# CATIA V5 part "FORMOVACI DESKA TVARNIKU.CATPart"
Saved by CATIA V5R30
Part number: FORMOVACI DESKA TVARNIKU
Bounding box of the stored display mesh (mm): x 0 to 56, y -248 to 248, z -173 to 173
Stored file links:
  C:\Users\ondra\Desktop\PŘÍLOHA P III\CATIA\FORMOVACI DESKA TVARNIKU.CATPart
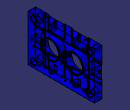
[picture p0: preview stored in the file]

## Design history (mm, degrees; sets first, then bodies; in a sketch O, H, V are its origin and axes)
Set1
  DatumSurface1 to DatumSurface42 "K20/346x"
  Plane1: type Tangent, Support DatumSurface41, RefPoint vertex [face of DatumSurface42]
  Plane2: type Tangent, Support DatumSurface39, RefPoint vertex [face of DatumSurface38]
  Plane3: type Offset, RefPlane yz-plane, Offset 56
  Join1: Elements (DatumSurface1; DatumSurface2; DatumSurface3; DatumSurface4; DatumSurface5; DatumSurface6; DatumSurface7; DatumSurface8; DatumSurface9; DatumSurface10; DatumSurface11; DatumSurface12; DatumSurface13; DatumSurface14; DatumSurface15; DatumSurface16; DatumSurface17; DatumSurface18; DatumSurface19; DatumSurface20; DatumSurface21; DatumSurface22; DatumSurface23; DatumSurface24; DatumSurface25; DatumSurface26; DatumSurface27; DatumSurface28; DatumSurface29; DatumSurface30; DatumSurface31; DatumSurface32; DatumSurface33; DatumSurface34; DatumSurface35; DatumSurface36; DatumSurface37; DatumSurface38; DatumSurface39; DatumSurface40; DatumSurface41; DatumSurface42)
Body1 (main body)
  DatumPoint1
  CloseSurface1: CloseElement Join1
  Sketch1 on {plane type Tangent, Support face of CloseSurface1, RefPoint vertex of DatumPoint1}, origin (0, -88.524, 0), H (0, 1, 0), V (0, 0, -1)
    point P1 (0, 0)
    reference projected point E1 (0, 0) from vertex of DatumPoint1
    coincidence: E1 P1
  Hole1: placed by Sketch1, at (56, -88.524, 0) direction (-1, 0, 0), diameter 130, through (limit type 6), counterbore diameter 140, counterbore depth 10
  Sketch2, origin (0, 0, 0), H (0, 1, 0), V (0, 0, -1), geometry linked from another document
  UserPattern1: of Hole1, copies 2, at the points of Sketch2
  Fillet1: radius 1, on edge [face of Hole1 | face of Hole1] (x2); edge [face of UserPattern1 | face of UserPattern1]; face of UserPattern1
  Plane4: type Offset, RefPlane yz-plane, Offset 56
  Sketch3 on Plane4, origin (56, 0, 0), H (0, 1, 0), V (0, 0, 1)
    point P1 (0, 0)
    coincidence: P1 O
  Sketch4 on {plane type Tangent, Support face of CloseSurface1, RefPoint Sketch3.P1}, origin (56, 0, 0), H (0, 1, 0), V (0, 0, -1)
    point P1 (0, 0)
    reference projected point E1 (0, 0) from Sketch3.P1
    coincidence: E1 P1
  Hole2: placed by Sketch4, at (56, 0, 0) direction (-1, 0, 0), diameter 18, through (limit type 6), counterbore diameter 22, counterbore depth 6
  Sketch5 on Plane4, origin (56, 0, 0), H (0, 1, 0), V (0, 0, 1)
    reference projected circle E1 centre (0, 0) radius 11 from edge [face of Hole2 | face of CloseSurface1]
    line L1 (-2, 10.8167) -> (-2, 16.0167)
    point P1 (-2, 10.8167)
    line L2 (-2, 16.0167) -> (2, 16.0167)
    line L3 (2, 16.0167) -> (2, 10.8167)
    point P4 (2, 10.8167)
    line L4 (2, 10.8167) -> (-2, 10.8167)
    point P5 (2, 10.8167)
    length L2 = 4
    length L3 = 5.2
    coincidence: P1 E1, P4 E1, P5 L3, P5 E1, P4 P5
    vertical: L1 V, L3 V
    horizontal: L2 H
    symmetry: L1 L3 V
  Pocket1: profile Sketch5, direction (-1, 0, 0), length 6
  Sketch6, origin (-1.2715, 23.524, 0), H (0, 0, 1), V (1, 0, 0), geometry linked from another document
  Pocket2: profile Sketch6, direction (0, -1, 0), length 6.1, opposite side through (limit type 6)
  DatumSurface43
  Sketch7, origin (-1.2715, -23.524, 0), H (0, 0, -1), V (1, 0, 0), geometry linked from another document
  Pocket3: profile Sketch7, direction (0, 1, 0), length 6.1, opposite side through (limit type 6)
  DatumSurface44
  Sketch8 on face of DatumSurface43, origin (56.0003, 0, 0), H (0, 1, 0), V (0, 0, 1)
    reference projected circle E1 centre (88.524, 0) radius 70 from face of DatumSurface44
    line L1 (158.4794, -2.5) -> (165.4794, -2.5)
    point P1 (158.4794, -2.5)
    line L2 (165.4794, -2.5) -> (165.4794, 2.5)
    line L3 (165.4794, 2.5) -> (158.4794, 2.5)
    point P4 (158.4794, 2.5)
    line L4 (158.4794, 2.5) -> (158.4794, -2.5)
    length L2 = 5
    length L3 = 7
    coincidence: P1 E1, P4 E1
    horizontal: L1 H, L3 H
    vertical: L2 V, L4 V
    symmetry: L1 L3 H
  Pocket4: profile Sketch8, direction (-1, 0, 0), length 7
  DatumSurface45
  Mirror1: of Pocket4, about zx-plane
  DatumSurface46
  Sketch9 on face of DatumSurface45, origin (-66, 0, 0), H (0, 1, 0), V (0, 0, 1)
    reference projected circle E1 centre (88.524, 0) radius 70 from face of DatumSurface46
    line L1 (158.4794, -2.5) -> (165.4794, -2.5)
    point P1 (158.4794, -2.5)
    line L2 (165.4794, -2.5) -> (165.4794, 2.5)
    line L3 (165.4794, 2.5) -> (158.4794, 2.5)
    point P4 (158.4794, 2.5)
    line L4 (158.4794, 2.5) -> (158.4794, -2.5)
    point P5 (158.4794, -2.5)
    length L3 = 7
    length L2 = 5
    coincidence: P1 E1, P4 E1, P5 L1
    horizontal: L1 H, L3 H
    vertical: L2 V, L4 V
    symmetry: L3 L1 H
  Plane5: type Offset, RefPlane zx-plane, Offset 248, reversed
  DatumSurface47
  Sketch10 on Plane5, origin (0, -248, 0), H (-1, 0, 0), V (0, 0, 1)
  Pocket5: profile Sketch10, direction (0, 1, 0), length 71
  Plane6: type Offset, RefPlane xy-plane, Offset 173
  DatumSurface48
  DatumSurface49
  Sketch11 on Plane6, origin (0, 0, 173), H (1, 0, 0), V (0, 1, 0)
  Pocket6: profile Sketch11, direction (0, 0, -1), length 101.008
  Mirror2: of Pocket5, about zx-plane
  Mirror3: of Pocket6, about xy-plane
  DatumSurface50
  Sketch12 on face of Pocket6, origin (7.4573, 0, 0), H (0, -1, 0), V (0, 0, 1)
    point P1 (79.524, 153)
    line L1 (79.524, 153) -> (97.524, 153)
    line L2 (97.524, 153) -> (97.524, 118)
    line L3 (97.524, 118) -> (79.524, 118)
    line L4 (79.524, 118) -> (79.524, 153)
    point P2 (97.524, 153)
    point P3 (97.524, 118)
    point P4 (79.524, 118)
    reference projected line E1 (148.524, 173) -> (28.524, 173) from edge [face of CloseSurface1 | face of Pocket6]
    point P5 (97.524, -118)
    point P6 (97.524, -153)
    line L5 (97.524, -153) -> (97.524, -118)
    point P7 (79.524, -153)
    point P8 (79.524, -118)
    line L6 (79.524, -118) -> (79.524, -153)
    line L7 (79.524, -153) -> (97.524, -153)
    point P9 (79.524, -118)
    point P10 (97.524, -118)
    line L8 (97.524, -118) -> (79.524, -118)
    line L9 (233, -9) -> (198, -9)
    line L10 (198, -9) -> (198, 9)
    line L11 (198, 9) -> (233, 9)
    line L12 (233, 9) -> (233, -9)
    reference projected line E2 (248, -47.5) -> (248, 47.5) from edge [face of CloseSurface1 | face of Pocket5]
    reference projected circle E3 centre (88.524, 0) radius 70 from face of DatumSurface50
    construction line L13 (88.524, 0) -> (88.524, 20.512)
    point P15 (88.524, 0)
    length L4 = 35
    length L1 = 18
    distance L1 E1 = 20
    distance E2 L12 = 15
    length L11 = 35
    length L12 = 18
    horizontal: L1 H, L3 H, L9 H, L11 H
    vertical: L2 V, L4 V, L10 V, L12 V, L13 V
    symmetry: P3 P5 H, P2 P6 H, L2 L5 H, P1 P7 H, P4 P8 H, L4 L6 H, L1 L7 H, P4 P9 H, P3 P10 H, L3 L8 H, L9 L11 H, L4 L2 L13
    concentricity: P15 E3
    coincidence: P5 P10, P8 P9
  Pocket7: profile Sketch12, direction (1, 0, 0), length 43, opposite side through (limit type 6)
  Sketch13 on Plane6, origin (0, 0, 173), H (1, 0, 0), V (0, 1, 0)
    point P1 (13, 165)
    point P2 (13, -165)
    construction line L1 (13, -165) -> (13, 165)
    distance P2 P1 = 330
    vertical: L1 V
    symmetry: P2 P1 H
  Sketch14 on {plane type Tangent, Support face of CloseSurface1, RefPoint Sketch13.P2}, origin (28, -115, 173), H (1, 0, 0), V (0, -1, 0)
    point P1 (-15, 50)
    reference projected point E1 (-15, 50) from Sketch13.P2
    coincidence: E1 P1
  Hole3: placed by Sketch14, at (13, -165, 173) direction (0, 0, -1), diameter 8.376, through (limit type 6), counterbore diameter 16, counterbore depth 17, threaded "M10", thread diameter 10, thread depth 7, pitch 1.5
  Sketch15 on Plane5, origin (0, -248, 0), H (-1, 0, 0), V (0, 0, 1)
    point P1 (-13, -71)
    point P2 (-13, 71)
    construction line L1 (-13, -71) -> (-13, 71)
    reference projected line E1 (-56, -173) -> (-56, 173) from edge [face of CloseSurface1 | face of CloseSurface1]
    length L1 = 142
    distance P2 E1 = 43
    vertical: L1 V
    symmetry: P2 P1 H
  Sketch16 on {plane type Tangent, Support face of CloseSurface1, RefPoint Sketch15.P1}, origin (28, -248, -75), H (1, 0, 0), V (0, 0, -1)
    point P1 (-15, -4)
    reference projected point E1 (-15, -4) from Sketch15.P1
    coincidence: E1 P1
  Hole4: placed by Sketch16, at (13, -248, -71) direction (0, 1, 0), diameter 8.376, through (limit type 3), counterbore diameter 14, counterbore depth 3, threaded "M10", thread diameter 10, thread depth 9, pitch 1.5
  UserPattern2: of Hole4, copies 2, at the points of Sketch15
  Sketch17 on {plane type Tangent, Support face of CloseSurface1, RefPoint Sketch13.P1}, origin (12, 165, 173), H (1, 0, 0), V (0, -1, 0)
    point P1 (1, 0)
    reference projected point E1 (1, 0) from Sketch13.P1
    coincidence: E1 P1
  Hole5: placed by Sketch17, at (13, 165, 173) direction (0, 0, -1), diameter 8.376, through (limit type 3), counterbore diameter 14, counterbore depth 3, threaded "M10", thread diameter 10, thread depth 9, pitch 1.5
  Plane7: type Offset, RefPlane Plane5, Offset 496
  Plane8: type Offset, RefPlane Plane6, Offset 346, reversed
  Mirror4: of Pocket7, about zx-plane
  DatumSurface51 to DatumSurface58
  Sketch18 on face of Mirror2, origin (3.6725, 0, 0), H (0, -1, 0), V (0, 0, 1)
    reference projected circle E1 centre (-240, 41) radius 3.75 from face of DatumSurface51
    reference projected circle E3 centre (-185, 41) radius 3.75 from face of DatumSurface52
    reference projected circle E5 centre (-240, -41) radius 3.75 from face of DatumSurface53
    reference projected circle E7 centre (-185, -41) radius 3.75 from face of DatumSurface54
    reference projected circle E9 centre (185, 41) radius 3.75 from face of DatumSurface55
    reference projected circle E11 centre (240, 41) radius 3.75 from face of DatumSurface56
    reference projected circle E13 centre (185, -41) radius 3.75 from face of DatumSurface57
    reference projected circle E15 centre (240, -41) radius 3.75 from face of DatumSurface58
    point P1 (185, -41)
    point P2 (240, -41)
    point P3 (240, 41)
    point P4 (185, 41)
    point P5 (-240, -41)
    point P6 (-185, -41)
    point P7 (-185, 41)
    point P8 (-240, 41)
    concentricity: P1 E13, P2 E15, P3 E11, P4 E9, P5 E5, P6 E7, P7 E3, P8 E1
  Sketch19 on face of Mirror2, origin (3.6725, 240, -41), H (0, 1, 0), V (0, 0, -1)
    point P1 (0, 0)
    reference projected point E1 (0, 0) from Sketch18.P5
    coincidence: E1 P1
  Hole6: placed by Sketch19, at (3.6725, 240, -41) direction (1, 0, 0), diameter 4.134, depth 15, V-bottom angle 120, threaded "M5", thread diameter 5, thread depth 13, pitch 0.8
  UserPattern3: of Hole6, copies 8, at the points of Sketch18
  DatumSurface59 to DatumSurface74
  Sketch20 on face of Mirror3, origin (7.4573, 0, 0), H (0, -1, 0), V (0, 0, 1)
    reference projected circle E1 centre (-140.524, 163.9919) radius 4.4 from face of DatumSurface59
    reference projected circle E3 centre (-140.524, 79.9919) radius 4.4 from face of DatumSurface60
    reference projected circle E5 centre (-36.524, 79.9919) radius 4.4 from face of DatumSurface61
    reference projected circle E7 centre (-36.524, 163.9919) radius 4.4 from face of DatumSurface62
    reference projected circle E9 centre (36.524, 79.9919) radius 4.4 from face of DatumSurface63
    reference projected circle E11 centre (36.524, 163.9919) radius 4.4 from face of DatumSurface64
    reference projected circle E13 centre (140.524, 163.9919) radius 4.4 from face of DatumSurface65
    reference projected circle E15 centre (140.524, 79.9919) radius 4.4 from face of DatumSurface66
    reference projected circle E17 centre (36.524, -163.9919) radius 4.4 from face of DatumSurface67
    reference projected circle E19 centre (36.524, -79.9919) radius 4.4 from face of DatumSurface68
    reference projected circle E21 centre (140.524, -79.9919) radius 4.4 from face of DatumSurface69
    reference projected circle E23 centre (140.524, -163.9919) radius 4.4 from face of DatumSurface70
    reference projected circle E25 centre (-140.524, -163.9919) radius 4.4 from face of DatumSurface71
    reference projected circle E27 centre (-140.524, -79.9919) radius 4.4 from face of DatumSurface72
    reference projected circle E29 centre (-36.524, -79.9919) radius 4.4 from face of DatumSurface73
    reference projected circle E31 centre (-36.524, -163.9919) radius 4.4 from face of DatumSurface74
    point P1 (-140.524, -163.9919)
    point P2 (-140.524, -79.9919)
    point P3 (-36.524, -163.9919)
    point P4 (-36.524, -79.9919)
    point P5 (36.524, -79.9919)
    point P6 (36.524, -163.9919)
    point P7 (140.524, -163.9919)
    point P8 (140.524, -79.9919)
    point P9 (140.524, 79.9919)
    point P10 (140.524, 163.9919)
    point P11 (36.524, 163.9919)
    point P12 (36.524, 79.9919)
    point P13 (-140.524, 163.9919)
    point P14 (-36.524, 163.9919)
    point P15 (-36.524, 79.9919)
    point P16 (-140.524, 79.9919)
    concentricity: P1 E25, P2 E27, P3 E31, P4 E29, P5 E19, P6 E17, P7 E23, P8 E21, P9 E15, P10 E13, P11 E11, P12 E9, P13 E1, P14 E7, P15 E5, P16 E3
  Sketch21 on face of Mirror3, origin (7.4573, 140.524, -163.9919), H (0, 1, 0), V (0, 0, -1)
    point P1 (0, 0)
    reference projected point E1 (0, 0) from Sketch20.P1
    coincidence: E1 P1
  Hole7: placed by Sketch21, at (7.4573, 140.524, -163.9919) direction (1, 0, 0), diameter 4.917, depth 15, V-bottom angle 120, threaded "M6", thread diameter 6, thread depth 13, pitch 1
  UserPattern4: of Hole7, copies 16, at the points of Sketch20
  Plane9: type Offset, RefPlane yz-plane, Offset 4.328, reversed
  Plane10: type Offset, RefPlane yz-plane, Offset 2.543, reversed
  Plane11: type Offset, RefPlane zx-plane, Offset 88.254
  Plane12: type Offset, RefPlane zx-plane, Offset 88.254, reversed
  DatumCurve1
  DatumCurve2
  Sketch22 on face of Mirror2, origin (3.6725, 0, 0), H (0, -1, 0), V (0, 0, 1)
    reference projected line E1 (-243.5, 7) -> (-227.5, 7) from edge of DatumCurve1
    reference projected line E2 (-227.5, -7) -> (-243.5, -7) from edge of DatumCurve2
    reference projected line E3 (-248, -47.5) -> (-248, 47.5) from edge [face of Mirror2 | face of CloseSurface1]
    point P7 (-232.5199, -7)
    line L1 (-232.5199, -7) -> (-248, -7)
    line L2 (-248, -7) -> (-248, 7)
    line L3 (-248, 7) -> (-232.5199, 7)
    line L4 (-232.5199, 7) -> (-232.5199, -7)
    point P8 (-248, -7)
    point P9 (-248, 7)
    point P10 (-232.5199, 7)
    point P11 (248, -7)
    point P12 (232.5199, -7)
    line L5 (232.5199, -7) -> (248, -7)
    point P13 (248, 7)
    line L6 (248, -7) -> (248, 7)
    point P14 (232.5199, 7)
    line L7 (248, 7) -> (232.5199, 7)
    line L8 (232.5199, 7) -> (232.5199, -7)
    coincidence: P7 E2, P9 E3, P9 E1
    horizontal: L1 H, L3 H
    vertical: L2 V, L4 V
    symmetry: P8 P11 V, P7 P12 V, L1 L5 V, P9 P13 V, L2 L6 V, P10 P14 V, L3 L7 V, L4 L8 V
  Pocket8: profile Sketch22, direction (1, 0, 0), length 3
  DatumCurve3
  DatumCurve4
  Sketch23 on face of Pocket6, origin (7.4573, 0, 0), H (0, -1, 0), V (0, 0, 1)
    reference projected line E1 (-79.524, 153) -> (-97.524, 153) from edge [face of Pocket6 | face of Mirror4]
    reference projected line E2 (-81.254, 168.5) -> (-81.254, 152.5) from edge of DatumCurve3
    reference projected line E3 (-95.254, 152.5) -> (-95.254, 168.5) from edge of DatumCurve4
    reference projected line E4 (-28.524, 173) -> (-148.524, 173) from edge [face of CloseSurface1 | face of Pocket6]
    point P9 (-95.254, 153)
    line L1 (-95.254, 153) -> (-81.254, 153)
    line L2 (-81.254, 153) -> (-81.254, 173)
    line L3 (-81.254, 173) -> (-95.254, 173)
    line L4 (-95.254, 173) -> (-95.254, 153)
    point P10 (-81.254, 153)
    point P11 (-81.254, 173)
    point P12 (-95.254, 173)
    point P13 (95.254, 173)
    point P14 (81.254, 173)
    line L5 (81.254, 173) -> (95.254, 173)
    point P15 (81.254, 153)
    line L6 (81.254, 153) -> (81.254, 173)
    point P16 (95.254, 153)
    line L7 (95.254, 173) -> (95.254, 153)
    line L8 (95.254, 153) -> (81.254, 153)
    coincidence: P9 E3, P9 E1, P11 E4, P11 E2
    horizontal: L1 H, L3 H
    vertical: L2 V, L4 V
    symmetry: P12 P13 V, P11 P14 V, L3 L5 V, P10 P15 V, L2 L6 V, P9 P16 V, L4 L7 V, L1 L8 V
  Pocket9: profile Sketch23, direction (1, 0, 0), length 1
  Mirror5: of Pocket9, about xy-plane
  DatumSurface75 to DatumSurface78
  Sketch24 on face of Pocket6, origin (7.4573, 0, 0), H (0, -1, 0), V (0, 0, 1)
    reference projected circle E1 centre (-88.254, 168) radius 3.75 from face of DatumSurface75
    reference projected circle E3 centre (88.254, 168) radius 3.75 from face of DatumSurface76
    reference projected circle E5 centre (-88.254, -168) radius 3.75 from face of DatumSurface77
    reference projected circle E7 centre (88.254, -168) radius 3.75 from face of DatumSurface78
    point P1 (-88.254, -168)
    point P2 (88.254, -168)
    point P3 (88.254, 168)
    point P4 (-88.254, 168)
    concentricity: P1 E5, P2 E7, P3 E3, P4 E1
  Sketch25 on end face of Pocket9, origin (8.4573, -88.254, 168), H (0, 1, 0), V (0, 0, -1)
    point P1 (0, 0)
    reference projected point E1 (0, 0) from Sketch24.P3
    coincidence: E1 P1
  Hole8: placed by Sketch25, at (8.4573, -88.254, 168) direction (1, 0, 0), diameter 4.134, depth 11, V-bottom angle 120, threaded "M5", thread diameter 5, thread depth 9, pitch 0.8
  UserPattern5: of Hole8, copies 4, at the points of Sketch24
  DatumSurface79
  DatumSurface80
  Sketch26 on face of Pocket5, origin (3.6725, 0, 0), H (0, -1, 0), V (0, 0, 1)
    reference projected circle E1 centre (-243, 0) radius 3.75 from face of DatumSurface79
    reference projected circle E3 centre (243, 0) radius 3.75 from face of DatumSurface80
    point P1 (243, 0)
    point P2 (-243, 0)
    concentricity: P1 E3, P2 E1
  Sketch27 on end face of Pocket8, origin (6.6725, -243, 0), H (0, 1, 0), V (0, 0, -1)
    point P1 (0, 0)
    reference projected point E1 (0, 0) from Sketch26.P1
    coincidence: E1 P1
  Hole9: placed by Sketch27, at (6.6725, -243, 0) direction (1, 0, 0), diameter 4.134, depth 11, V-bottom angle 120, threaded "M5", thread diameter 5, thread depth 9, pitch 0.8
  UserPattern6: of Hole9, copies 2, at the points of Sketch26
  DatumSurface81 to DatumSurface84
  Sketch28 on face of Pocket6, origin (7.4573, 0, 0), H (0, -1, 0), V (0, 0, 1)
    reference projected circle E2 centre (-88.254, 156) radius 2.2913 from face of DatumSurface81
    reference projected circle E4 centre (88.254, 156) radius 2.2913 from face of DatumSurface82
    reference projected circle E6 centre (88.254, -156) radius 2.2913 from face of DatumSurface83
    reference projected circle E8 centre (-88.254, -156) radius 2.2913 from face of DatumSurface84
    point P1 (-88.254, -156)
    point P2 (88.254, -156)
    point P3 (88.254, 156)
    point P4 (-88.254, 156)
    concentricity: P1 E8, P2 E6, P3 E4, P4 E2
  Sketch29 on end face of Pocket9, origin (8.4573, -88.254, 156), H (0, 1, 0), V (0, 0, -1)
    point P1 (0, 0)
    reference projected point E1 (0, 0) from Sketch28.P3
    coincidence: E1 P1
  Hole10: placed by Sketch29, at (8.4573, -88.254, 156) direction (1, 0, 0), diameter 13.5, depth 5.2
  Sketch30 on face of Mirror5, origin (8.4573, -88.254, -156), H (0, 1, 0), V (0, 0, -1)
    point P1 (0, 0)
    reference projected point E1 (0, 0) from Sketch28.P2
    coincidence: E1 P1
  Hole11: placed by Sketch30, at (8.4573, -88.254, -156) direction (1, 0, 0), diameter 13.5, depth 5.2
  Sketch31 on face of Mirror5, origin (8.4573, 88.254, -156), H (0, 1, 0), V (0, 0, -1)
    point P1 (0, 0)
    reference projected point E1 (0, 0) from Sketch28.P1
    coincidence: E1 P1
  Hole12: placed by Sketch31, at (8.4573, 88.254, -156) direction (1, 0, 0), diameter 13.5, depth 5.2
  Sketch32 on end face of Pocket9, origin (8.4573, 88.254, 156), H (0, 1, 0), V (0, 0, -1)
    point P1 (0, 0)
    reference projected point E1 (0, 0) from Sketch28.P4
    coincidence: E1 P1
  Hole13: placed by Sketch32, at (8.4573, 88.254, 156) direction (1, 0, 0), diameter 13.5, depth 5.2
  DatumSurface85
  DatumSurface86
  Sketch33 on face of Pocket5, origin (3.6725, 0, 0), H (0, -1, 0), V (0, 0, 1)
    reference projected circle E2 centre (-231, 0) radius 2.2913 from face of DatumSurface85
    reference projected circle E4 centre (231, 0) radius 2.2913 from face of DatumSurface86
    point P1 (231, 0)
    point P2 (-231, 0)
    concentricity: P1 E4, P2 E2
  Sketch34 on end face of Pocket8, origin (6.6725, -232.5199, 0), H (0, 1, 0), V (0, 0, -1)
    point P1 (1.5199, 0)
    reference projected point E1 (1.5199, 0) from Sketch33.P1
    coincidence: E1 P1
  Hole14: placed by Sketch34, at (6.6725, -231, 0) direction (1, 0, 0), diameter 13.5, depth 5.2
  Sketch35 on end face of Pocket8, origin (6.6725, 232.5199, 0), H (0, 1, 0), V (0, 0, -1)
    point P1 (-1.5199, 0)
    reference projected point E1 (-1.5199, 0) from Sketch33.P2
    coincidence: E1 P1
  Hole15: placed by Sketch35, at (6.6725, 231, 0) direction (1, 0, 0), diameter 13.5, depth 5.2
  DatumSurface87
  Sketch36 on xy-plane, origin (0, 0, 0), H (1, 0, 0), V (0, 1, 0)
    reference projected circle E1 centre (25, 0) radius 7 from face of DatumSurface87
    point P1 (25, 0)
    concentricity: P1 E1
  Sketch37 on {plane type Tangent, Support face of CloseSurface1, RefPoint Sketch36.P1}, origin (25, 0, 0), H (1, 0, 0), V (0, -1, 0)
    point P1 (0, 0)
    reference projected point E1 (0, 0) from Sketch36.P1
    coincidence: E1 P1
  Hole16: placed by Sketch37, at (25, 0, 173) direction (0, 0, -1), diameter 6.647, depth 13, V-bottom angle 120, threaded "M8", thread diameter 8, thread depth 11, pitch 1.25
  Mirror6: of Hole16, about xy-plane
  Sketch38 on {plane type Tangent, Support face of CloseSurface1, RefPoint Sketch15.P1}, origin (13, -248, -71), H (1, 0, 0), V (0, 0, 1)
    point P1 (0, 0)
    reference projected point E1 (0, 0) from Sketch15.P1
    coincidence: E1 P1
  Hole17: placed by Sketch38, at (13, 248, -71) direction (0, -1, 0), diameter 8.376, depth 12, counterbore diameter 14, counterbore depth 3, threaded "M10", thread diameter 10, thread depth 9, pitch 1.5
  UserPattern7: of Hole17, copies 2, at the points of Sketch15
  Sketch39 on {plane type Tangent, Support face of CloseSurface1, RefPoint Sketch13.P2}, origin (13, -165, 173), H (1, 0, 0), V (0, 1, 0)
    point P1 (0, 0)
    reference projected point E1 (0, 0) from Sketch13.P2
    coincidence: E1 P1
  Hole18: placed by Sketch39, at (13, -165, -173) direction (0, 0, 1), diameter 8.376, depth 12, V-bottom angle 120, counterbore diameter 14, counterbore depth 3, threaded "M10", thread diameter 10, thread depth 9, pitch 1.5
  Sketch40 on {plane type Tangent, Support face of CloseSurface1, RefPoint Sketch13.P1}, origin (13, 165, 173), H (1, 0, 0), V (0, 1, 0)
    point P1 (0, 0)
    reference projected point E1 (0, 0) from Sketch13.P1
    coincidence: E1 P1
  Hole19: placed by Sketch40, at (13, 165, -173) direction (0, 0, 1), diameter 8.376, depth 24, counterbore diameter 16, counterbore depth 17, threaded "M10", thread diameter 10, thread depth 7, pitch 1.5
  Plane13: type Offset, RefPlane Plane5, Offset 3
  Plane14: type Offset, RefPlane Plane7, Offset 3, reversed
  Plane15: type Offset, RefPlane Plane6, Offset 3, reversed
  Plane16: type Offset, RefPlane Plane6, Offset 17, reversed
  Plane17: type Offset, RefPlane Plane8, Offset 17
  Plane18: type Offset, RefPlane Plane8, Offset 3
Body2
  Plane19: type Offset, RefPlane Plane16, Offset 7, reversed
  Plane20: type Offset, RefPlane Plane18, Offset 6
  Plane21: type Offset, RefPlane Plane15, Offset 6, reversed
  Plane22: type Offset, RefPlane Plane17, Offset 7
  Plane23: type Offset, RefPlane Plane14, Offset 6, reversed
  Plane24: type Offset, RefPlane Plane13, Offset 6
  Sketch41 on Plane19, origin (0, 0, 149), H (1, 0, 0), V (0, 1, 0)
    projected circle E1 centre (13, -165) radius 4.188 from edge [face of Hole3 | face of Hole3]
  Pad1: profile Sketch41, direction (0, 0, 1), up to Plane20
  Sketch42 on Plane21, origin (0, 0, 164), H (1, 0, 0), V (0, 1, 0)
    projected circle E1 centre (13, 165) radius 4.188 from edge [face of Hole5 | face of Hole5]
  Pad2: profile Sketch42, direction (0, 0, 1), up to Plane22
  Sketch43 on Plane24, origin (0, -239, 0), H (-1, 0, 0), V (0, 0, 1)
    projected circle E1 centre (-13, 71) radius 4.188 from edge [face of UserPattern2 | face of UserPattern7]
    projected circle E2 centre (-13, -71) radius 4.188 from edge [face of Hole4 | face of Hole17]
  Pad3: profile Sketch43, direction (0, 1, 0), up to Plane23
